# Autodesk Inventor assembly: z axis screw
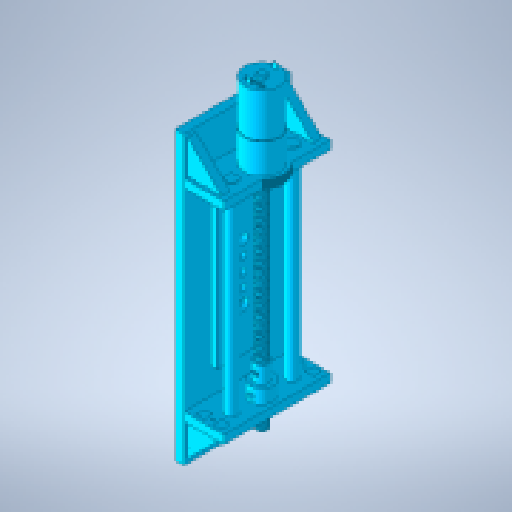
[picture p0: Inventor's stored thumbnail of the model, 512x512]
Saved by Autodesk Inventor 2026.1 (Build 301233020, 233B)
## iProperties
Created: 2026-10
Part Number: z axis screw
Document SubType Name: Assembly
Designer: hp
Author: hp
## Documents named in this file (15)
- C:\Users\hp\Documents\Inventor\DOM1_CartesianRobot\z axis screw.iam
- C:\Users\hp\Documents\Inventor\DOM1_CartesianRobot\small_Z_Back.ipt
- C:\Users\hp\Documents\Inventor\DOM1_CartesianRobot\small_Z_Buttom.ipt
- C:\Users\hp\Documents\Inventor\DOM1_CartesianRobot\small_Z_Top.ipt
- C:\Users\hp\Documents\Inventor\DOM1_CartesianRobot\rip_1.ipt
- C:\Users\hp\Documents\Inventor\DOM1_CartesianRobot\rip_2.ipt
- C:\Users\hp\Documents\Inventor\DOM1_CartesianRobot\rip_3.ipt
- C:\Users\hp\Documents\Inventor\DOM1_CartesianRobot\rip_4.ipt
- C:\Users\hp\Documents\Inventor\DOM1_CartesianRobot\8mm_Bar_150mm.ipt
- C:\Users\hp\Documents\Inventor\DOM1_CartesianRobot\8mm_Bar_150mm_1.ipt
- C:\Users\hp\Documents\Inventor\DOM1_CartesianRobot\688_bearing_1.ipt
- C:\Users\hp\Documents\Inventor\DOM1_CartesianRobot\Lead Screw T8X8X500_150.ipt
- C:\Users\hp\Documents\Inventor\DOM1_CartesianRobot\25GA370 red26.ipt
- C:\Users\hp\Documents\Inventor\DOM1_CartesianRobot\Coupling 4mm x 8mm.ipt
- C:\Users\hp\Documents\Inventor\Content Center Files\R2026\en-US\ISO 4017(1)\ISO 4017 - M2.5 x 5 - ISO.ipt
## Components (15 placed, 14 different names)
1. small_Z_Back:1
2. small_Z_Buttom:1 — Mate:1, Mate:2, Flush:1
3. small_Z_Top:1
4. rip_1:1 — Mate:5, Mate:6, Flush:3
5. rip_2:1 — Mate:3, Mate:4, Flush:2
6. rip_3:1 — Mate:9, Mate:10, Flush:5
7. rip_4:1 — Mate:7, Mate:8, Flush:4
8. 8mm_Bar_150mm:1
9. 8mm_Bar_150mm_1:1
10. 688_bearing_1:1 — Mate:19
11. Lead Screw T8X8X500_150:1 — Mate:16, Mate:17, Mate:18
12. 25GA370 red26:1 — Mate:13, Mate:14, Mate:15, Mate:16, Mate:17
13. Coupling 4mm x 8mm:1 — Mate:18, Mate:19
14. ISO 4017 M2.5 x 5:1
15. ISO 4017 M2.5 x 5:2
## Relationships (22: Mate 17, Flush 5)
- Mate:1: small_Z_Buttom:1
- Mate:2: small_Z_Buttom:1
- Flush:1: small_Z_Buttom:1
- Mate:3: rip_2:1
- Mate:4: rip_2:1
- Flush:2: rip_2:1
- Mate:5: rip_1:1
- Mate:6: rip_1:1
- Flush:3: rip_1:1
- Mate:7: rip_4:1
- Mate:8: rip_4:1
- Flush:4: rip_4:1
- Mate:9: rip_3:1
- Mate:10: rip_3:1
- Flush:5: rip_3:1
- Mate:13: 25GA370 red26:1
- Mate:14: 25GA370 red26:1
- Mate:15: 25GA370 red26:1
- Mate:16: Lead Screw T8X8X500_150:1 ↔ 25GA370 red26:1
- Mate:17: Lead Screw T8X8X500_150:1 ↔ 25GA370 red26:1
- Mate:18: Lead Screw T8X8X500_150:1 ↔ Coupling 4mm x 8mm:1
- Mate:19: 688_bearing_1:1 ↔ Coupling 4mm x 8mm:1
